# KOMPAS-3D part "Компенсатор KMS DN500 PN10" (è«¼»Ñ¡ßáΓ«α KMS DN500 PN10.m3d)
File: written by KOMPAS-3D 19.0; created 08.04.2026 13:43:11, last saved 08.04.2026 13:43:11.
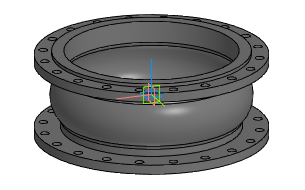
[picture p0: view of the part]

Document properties: Автор: Энергия; Полное имя файла: Z:\3.Личные\kachalov\3d для проектировщиков\7.1 Компенсатор\stp_Компенсатор KSM\Компенсатор KMS DN500 PN10.m3d

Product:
- Part/product: Компенсатор KMS DN500 PN10

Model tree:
1. Операция без истории:1  (labels: Компенсатор KMS DN500 PN10)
